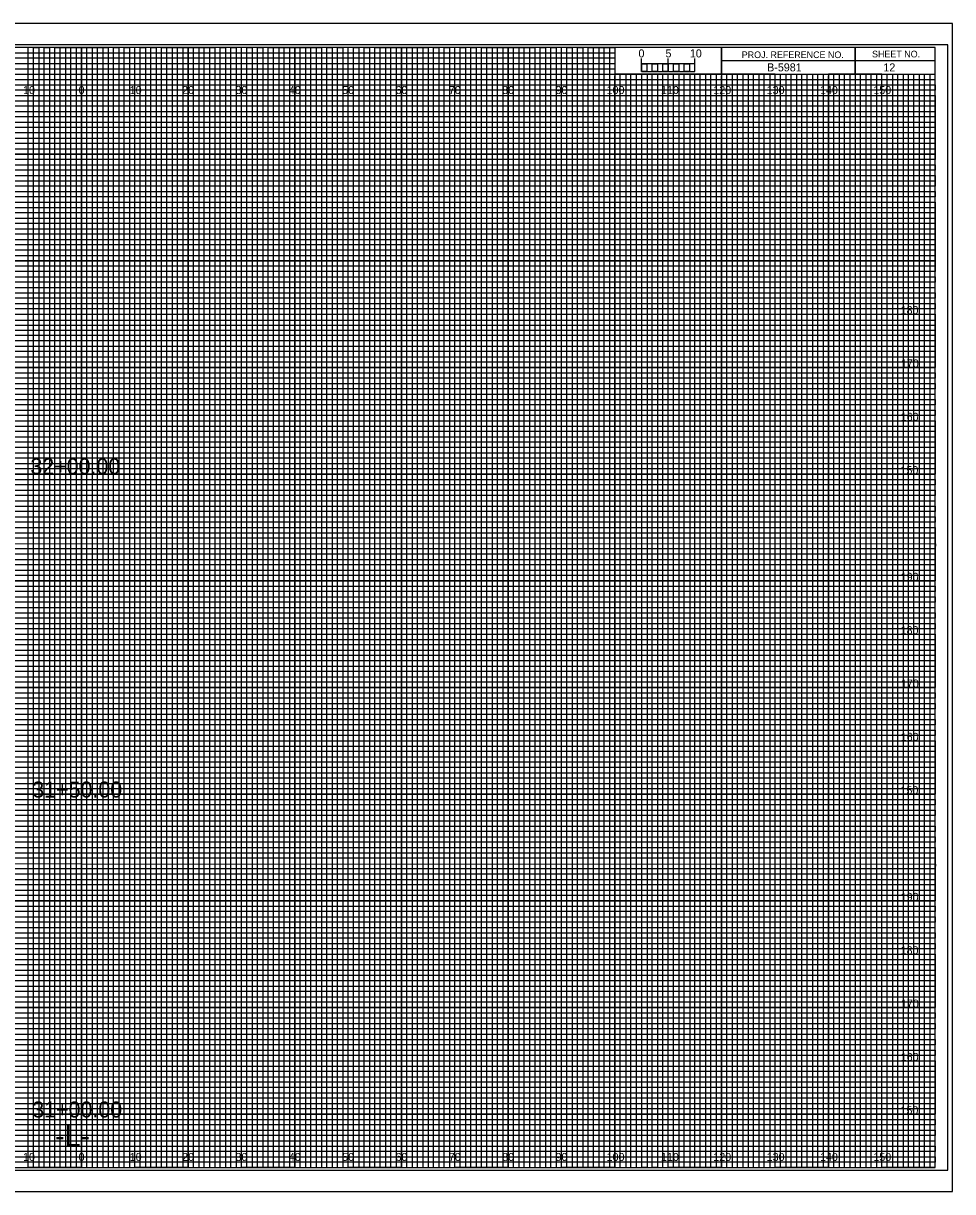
# Model space of a CAD drawing. Extents: x -13 to 323, y -5 to 434.
# Drawn here: x 149.1 to 323.3, y -4.5 to 214.5 of the extents above; entities that cross this region are included whole.
import ezdxf

# ---------------------------------------------------------------- set-up
doc = ezdxf.new("R2010")
doc.units = 0
for name, color, linetype in [('Exist Cross Section Cell', 7, 'Continuous'), ('Exist XS Center Line Elevation Label', 7, 'Continuous'), ('Exist XS Ground Line', 7, 'Continuous'), ('Prop CMT Concrete Structures', 7, 'Continuous'), ('Prop CMT Guardrail Graphics', 7, 'Continuous'), ('Prop CMT Pvmt Course 1', 7, 'Continuous'), ('Prop CMT Pvmt Course 2', 7, 'Continuous'), ('Prop CMT Pvmt Course 3', 7, 'Continuous'), ('Prop CMT Pvmt Surface', 7, 'Continuous'), ('Prop CMT Shld Paved Course 1', 7, 'Continuous'), ('Prop CMT Shld Paved Course 2', 7, 'Continuous'), ('Prop CMT Shld Paved Course 3', 7, 'Continuous'), ('Prop CMT Subgrade Earthwork', 7, 'Continuous'), ('Prop XS Ditch Standard Text', 7, 'Continuous'), ('Prop XS SE Text', 7, 'Continuous'), ('Prop XS Side Slope Text', 7, 'Continuous'), ('Scratch_Level_0', 7, 'Continuous')]:
    doc.layers.add(name, color=color, linetype=linetype)

msp = doc.modelspace()

# ---------------------------------------------------------------- linework, layer by layer
at = {"layer": 'Exist XS Center Line Elevation Label'}
for points in [[(145, 0), (155, 0), (155, 210), (165, 210), (165, 0), (175, 0), (175, 210), (185, 210), (185, 0), (195, 0), (195, 210), (205, 210), (205, 0), (215, 0), (215, 210), (225, 210), (225, 0), (235, 0), (235, 210), (245, 210), (245, 0), (255, 0), (255, 210), (259.93, 210), (260, 210), (260, 205), (264.99, 205), (264.99, 0), (275, 0), (275, 205), (285, 205), (285, 0), (295, 0), (295, 205), (305, 205), (305, 0), (315, 0), (315, 205)], [(0, 205), (275, 205)], [(0, 185), (320, 185), (320, 195), (0, 195)], [(0, 165), (320, 165), (320, 175), (0, 175)], [(0, 145), (320, 145), (320, 155), (0, 155)], [(0, 125), (320, 125), (320, 135), (0, 135)], [(0, 105), (320, 105), (320, 115), (0, 115)], [(0, 85), (320, 85), (320, 95), (0, 95)], [(0, 65), (320, 65), (320, 75), (0, 75)], [(0, 45), (320, 45), (320, 55), (0, 55)], [(0, 25), (320, 25), (320, 35), (0, 35)], [(0, 5), (320, 5), (320, 15), (0, 15)]]:
    msp.add_lwpolyline(points, dxfattribs=at)
at = {"layer": 'Exist XS Ground Line'}
for p, q in [((150, 210), (140, 210)), ((150, 0), (150, 210)), ((170, 210), (160, 210)), ((160, 210), (160, 0)), ((170, 0), (170, 210)), ((190, 210), (180, 210)), ((180, 210), (180, 0)), ((190, 0), (190, 210)), ((210, 210), (200, 210)), ((200, 210), (200, 0)), ((210, 0), (210, 210)), ((230, 210), (220, 210)), ((220, 210), (220, 0)), ((230, 0), (230, 210)), ((250, 210), (240, 210)), ((240, 210), (240, 0)), ((250, 0), (250, 210)), ((260, 210), (260, 0)), ((270, 0), (270, 205)), ((290, 205), (280, 205)), ((280, 205), (280, 0)), ((290, 0), (290, 205)), ((310, 205), (300, 205)), ((300, 205), (300, 0)), ((310, 0), (310, 205)), ((160, 0), (150, 0)), ((180, 0), (170, 0)), ((200, 0), (190, 0)), ((220, 0), (210, 0)), ((240, 0), (230, 0)), ((260, 0), (250, 0)), ((280, 0), (270, 0)), ((300, 0), (290, 0)), ((320, 0), (310, 0)), ((320, 0), (320, 0))]:
    msp.add_line(p, q, dxfattribs=at)
for points in [[(0, 200), (320, 200), (320, 190), (0, 190)], [(0, 180), (320, 180), (320, 170), (0, 170)], [(0, 160), (320, 160), (320, 150), (0, 150)], [(0, 140), (320, 140), (320, 130), (0, 130)], [(0, 120), (320, 120), (320, 110), (0, 110)], [(0, 100), (320, 100), (320, 90), (0, 90)], [(0, 80), (320, 80), (320, 70), (0, 70)], [(0, 60), (320, 60), (320, 50), (0, 50)], [(0, 40), (320, 40), (320, 30), (0, 30)], [(0, 20), (320, 20), (320, 10), (0, 10)]]:
    msp.add_lwpolyline(points, dxfattribs=at)
at = {"layer": 'Prop CMT Pvmt Course 1'}
for p, q in [((323.3, 214.5), (-13.4, 214.5)), ((-13.4, -4.5), (323.3, -4.5))]:
    msp.add_line(p, q, dxfattribs=at)
at = {"layer": 'Prop CMT Pvmt Course 2'}
msp.add_lwpolyline([(-13.4, -4.5), (323.3, -4.5), (323.3, 214.5), (-13.4, 214.5)], close=True, dxfattribs=at)
at = {"layer": 'Prop CMT Pvmt Course 3'}
msp.add_lwpolyline([(-10.8, -0.5), (322.4, -0.5), (322.4, 210.5), (-10.8, 210.5)], close=True, dxfattribs=at)
at = {"layer": 'Prop CMT Shld Paved Course 1'}
for p, q in [((305, 210), (305, 205)), ((305, 205), (305, 210)), ((280, 207.5), (280, 205)), ((320, 207.49), (280, 207.49)), ((280, 205), (320, 205))]:
    msp.add_line(p, q, dxfattribs=at)
for points in [[(320, 210), (0, 210), (0, 0), (320, 0)], [(280, 210), (260, 210), (260, 205.03), (280, 205.03)], [(320, 210), (280, 210), (280, 205), (320, 205)]]:
    msp.add_lwpolyline(points, close=True, dxfattribs=at)
at = {"layer": 'Prop CMT Shld Paved Course 2'}
for p, q in [((267, 205), (266.01, 205)), ((266.01, 205), (266.01, 0)), ((267, 0), (267, 205)), ((269, 205), (268, 205)), ((268, 205), (268, 0)), ((269, 0), (269, 205)), ((266.01, 0), (265, 0)), ((268, 0), (267, 0))]:
    msp.add_line(p, q, dxfattribs=at)
for points in [[(150, 0), (151, 0), (151, 210), (152, 210), (152, 0)], [(152, 0), (153, 0), (153, 210), (154, 210), (154, 0)], [(155, 0), (156, 0), (156, 210), (157, 210), (157, 0)], [(157, 0), (158, 0), (158, 210), (159, 210), (159, 0)], [(160, 0), (161, 0), (161, 210), (162, 210), (162, 0)], [(162, 0), (163, 0), (163, 210), (164, 210), (164, 0)], [(165, 0), (166, 0), (166, 210), (167, 210), (167, 0)], [(167, 0), (168, 0), (168, 210), (169, 210), (169, 0)], [(170, 0), (171, 0), (171, 210), (172, 210), (172, 0)], [(172, 0), (173, 0), (173, 210), (174, 210), (174, 0)], [(175, 0), (176, 0), (176, 210), (177, 210), (177, 0)], [(177, 0), (178, 0), (178, 210), (179, 210), (179, 0)], [(180, 0), (181, 0), (181, 210), (182, 210), (182, 0)], [(182, 0), (183, 0), (183, 210), (184, 210), (184, 0)], [(185, 0), (186, 0), (186, 210), (187, 210), (187, 0)], [(187, 0), (188, 0), (188, 210), (189, 210), (189, 0)], [(190, 0), (191, 0), (191, 210), (192, 210), (192, 0)], [(192, 0), (193, 0), (193, 210), (194, 210), (194, 0)], [(195, 0), (196, 0), (196, 210), (197, 210), (197, 0)], [(197, 0), (198, 0), (198, 210), (199, 210), (199, 0)], [(200, 0), (201, 0), (201, 210), (202, 210), (202, 0)], [(202, 0), (203, 0), (203, 210), (204, 210), (204, 0)], [(205, 0), (206, 0), (206, 210), (207, 210), (207, 0)], [(207, 0), (208, 0), (208, 210), (209, 210), (209, 0)], [(210, 0), (211, 0), (211, 210), (212, 210), (212, 0)], [(212, 0), (213, 0), (213, 210), (214, 210), (214, 0)], [(215, 0), (216, 0), (216, 210), (217, 210), (217, 0)], [(217, 0), (218, 0), (218, 210), (219, 210), (219, 0)], [(220, 0), (221, 0), (221, 210), (222, 210), (222, 0)], [(222, 0), (223, 0), (223, 210), (224, 210), (224, 0)], [(225, 0), (226, 0), (226, 210), (227, 210), (227, 0)], [(227, 0), (228, 0), (228, 210), (229, 210), (229, 0)], [(230, 0), (231, 0), (231, 210), (232, 210), (232, 0)], [(232, 0), (233, 0), (233, 210), (234, 210), (234, 0)], [(235, 0), (236, 0), (236, 210), (237, 210), (237, 0)], [(237, 0), (238, 0), (238, 210), (239, 210), (239, 0)], [(240, 0), (241, 0), (241, 210), (242, 210), (242, 0)], [(242, 0), (243, 0), (243, 210), (244, 210), (244, 0)], [(245, 0), (246, 0), (246, 210), (247, 210), (247, 0)], [(247, 0), (248, 0), (248, 210), (249, 210), (249, 0)], [(250, 0), (251, 0), (251, 210), (252, 210), (252, 0)], [(252, 0), (253, 0), (253, 210), (254, 210), (254, 0)], [(255, 0), (256, 0), (256, 210), (257, 210), (257, 0)], [(257, 0), (258, 0), (258, 210), (259, 210), (259, 0)], [(260, 0), (261, 0), (261, 205), (262.02, 205), (262.02, 0)], [(262, 0), (263, 0), (263, 205), (263.99, 205), (263.99, 0)], [(270, 0), (270.98, 0), (270.98, 205), (272, 205), (272, 0)], [(272, 0), (273, 0), (273, 205), (274.05, 205), (274.05, 0)], [(275, 0), (276, 0), (276, 205), (277, 205), (277, 0)], [(277, 0), (278, 0), (278, 205), (279, 205), (279, 0)], [(280, 0), (281, 0), (281, 205), (282, 205), (282, 0)], [(282, 0), (283, 0), (283, 205), (284, 205), (284, 0)], [(285, 0), (286, 0), (286, 205), (287, 205), (287, 0)], [(287, 0), (288, 0), (288, 205), (289, 205), (289, 0)], [(290, 0), (291, 0), (291, 205), (292, 205), (292, 0)], [(292, 0), (293, 0), (293, 205), (294, 205), (294, 0)], [(295, 0), (296, 0), (296, 205), (297, 205), (297, 0)], [(297, 0), (298, 0), (298, 205), (299, 205), (299, 0)], [(300, 0), (301, 0), (301, 205), (302, 205), (302, 0)], [(302, 0), (303, 0), (303, 205), (304, 205), (304, 0)], [(305, 0), (306, 0), (306, 205), (307, 205), (307, 0)], [(307, 0), (308, 0), (308, 205), (309, 205), (309, 0)], [(310, 0), (311, 0), (311, 205), (312, 205), (312, 0)], [(312, 0), (313, 0), (313, 205), (314, 205), (314, 0)], [(315, 0), (316, 0), (316, 205), (317, 205), (317, 0)], [(317, 0), (318, 0), (318, 205), (319, 205), (319, 0)]]:
    msp.add_lwpolyline(points, dxfattribs=at)
at = {"layer": 'Prop CMT Shld Paved Course 3'}
for p, q in [((265, 205.49), (265, 207.9)), ((265, 206.9), (265, 207.9)), ((270, 205.49), (270, 207.9)), ((275, 205.49), (275, 207.9)), ((275, 206.9), (275, 207.9))]:
    msp.add_line(p, q, dxfattribs=at)
for points in [[(275, 206.9), (265, 206.9), (265, 205.49), (275, 205.49)], [(265, 206.9), (266, 206.9), (266, 205.49), (265, 205.49)], [(267, 206.9), (268, 206.9), (268, 205.49), (267, 205.49)], [(269, 206.9), (270, 206.9), (270, 205.49), (269, 205.49)], [(271, 206.9), (272, 206.9), (272, 205.49), (271, 205.49)], [(273, 206.9), (274, 206.9), (274, 205.49), (273, 205.49)]]:
    msp.add_lwpolyline(points, close=True, dxfattribs=at)
at = {"layer": 'Prop CMT Subgrade Earthwork'}
for p, q in [((150, 0), (150, 210)), ((160, 0), (160, 210)), ((170, 0), (170, 210)), ((180, 0), (180, 210)), ((190, 0), (190, 210)), ((200, 0), (200, 210)), ((210, 0), (210, 210)), ((220, 0), (220, 210)), ((230, 0), (230, 210)), ((240, 0), (240, 210)), ((250, 0), (250, 210)), ((260, 0), (260, 204.69)), ((270, 0), (270, 204.69)), ((280, 0), (280, 204.69)), ((290, 0), (290, 204.69)), ((300, 0), (300, 204.69)), ((310, 0), (310, 204.69)), ((0, 200), (320, 200)), ((0, 190), (320, 190)), ((0, 180), (320, 180)), ((0, 170), (320, 170)), ((0, 160), (320, 160)), ((0, 150), (320, 150)), ((0, 140), (320, 140)), ((0, 130), (320, 130)), ((0, 120), (320, 120)), ((0, 110), (320, 110)), ((0, 100), (320, 100)), ((0, 90), (320, 90)), ((0, 80), (320, 80)), ((0, 70), (320, 70)), ((0, 60), (320, 60)), ((0, 50), (320, 50)), ((0, 40), (320, 40)), ((0, 30), (320, 30)), ((0, 20), (320, 20)), ((0, 10), (320, 10))]:
    msp.add_line(p, q, dxfattribs=at)
at = {"layer": 'Scratch_Level_0'}
for p, q in [((0, 209), (260, 209)), ((260, 209), (260, 207.98)), ((260, 207.98), (0, 207.98)), ((0, 207), (260, 207)), ((260, 205.89), (0, 205.89)), ((260, 207), (260, 205.89)), ((0, 204), (320, 204))]:
    msp.add_line(p, q, dxfattribs=at)
for points in [[(0, 203), (270, 203), (320, 203), (320, 202), (0, 202)], [(0, 201), (320, 201), (320, 199), (0, 199)], [(0, 198), (320, 198), (320, 197), (0, 196.98)], [(0, 196), (320, 196), (320, 194), (0, 194)], [(0, 193), (320, 193), (320, 192), (0, 192)], [(0, 191), (320, 191), (320, 189), (0, 189)], [(0, 188), (320, 188), (320, 187), (0, 187)], [(0, 186), (320, 186), (320, 184), (0, 184)], [(0, 183), (320, 183), (320, 182), (0, 182)], [(0, 181), (320, 181), (320, 179), (0, 179)], [(0, 178), (320, 178), (320, 177), (0, 177)], [(0, 176), (320, 176), (320, 173.95), (320, 173), (320, 172), (0, 172)], [(0, 174), (320, 174), (320, 173), (0, 173)], [(0, 171), (320, 171), (320, 169), (0, 169.03)], [(0, 169.03), (320, 169), (320, 168), (0, 168)], [(0, 167), (320, 167), (320, 166), (0, 166)], [(0, 164), (320, 164), (320, 163), (0, 163)], [(0, 162), (320, 162), (320, 161), (0, 161)], [(-0.07, 158.89), (320, 158.89), (320, 157.88), (-0.07, 157.88)], [(0, 157), (320, 157), (320, 156), (0, 156)], [(0, 154), (320, 154), (320, 153), (0, 153)], [(0, 152), (320, 152), (320, 151), (0, 151)], [(0, 149), (320, 149), (320, 148), (0, 148)], [(0, 147), (320, 147), (320, 146), (0, 146)], [(0, 144), (320, 144), (320, 143), (0, 143)], [(0, 142), (320, 142), (320, 141), (0, 141)], [(0, 139), (320, 139), (319.99, 137.98), (0, 138)], [(0, 137), (320, 137), (320, 136), (0, 136)], [(0, 134), (320, 134), (320, 133), (0, 133)], [(0, 132), (320, 132), (320, 131), (0, 131)], [(0, 129), (320, 129), (320, 128), (0, 128)], [(0, 127), (320, 127), (320, 126), (0, 126)], [(0, 124), (320, 124), (320, 123), (0, 123)], [(0, 122), (320, 122), (320, 121), (0, 121)], [(0, 119), (320, 119), (320, 118), (0, 118)], [(0, 116.99), (320.07, 116.91), (320, 116), (0, 116)], [(0, 114), (320, 114), (320, 113), (0, 113)], [(0, 112), (320, 112), (320, 111), (0, 111)], [(0, 109), (320, 109), (320, 108), (0, 108)], [(0, 107), (320, 107), (320, 106), (0, 106)], [(0, 104), (320, 104), (320, 103), (0, 103)], [(0, 102), (320, 102), (320, 101), (0, 101)], [(0, 99), (320, 99), (320, 98), (0, 98)], [(0, 97), (320, 97), (320, 96), (0, 96)], [(0, 94), (320, 94), (320, 93), (0, 93)], [(0, 92), (320, 92), (320, 91), (0, 91)], [(0, 89), (320, 89), (320, 88), (0, 88)], [(0, 87), (320, 87), (320, 86), (0, 86)], [(0, 84), (320, 84), (320, 83), (0, 83)], [(0, 82), (320, 82), (320, 81), (0, 81)], [(0, 79), (320, 79), (319.99, 77.98), (0, 78)], [(0, 77), (320, 77), (320, 76), (0, 76)], [(0, 74), (320, 74), (320, 73), (0, 73)], [(0, 72), (320, 72), (320, 71), (0, 71)], [(0, 69), (320, 69), (320, 68), (0, 68)], [(0, 67), (320, 67), (320, 66), (0, 66)], [(0, 64), (320, 64), (320, 63), (0, 63)], [(0, 62), (320, 62), (320, 61), (0, 61)], [(0, 59), (320, 59), (320, 58), (0, 58)], [(0, 56.99), (320.07, 56.91), (320, 56), (0, 56)], [(0, 54), (320, 54), (320, 53), (0, 53)], [(0, 52), (320, 52), (320, 51), (0, 51)], [(0, 49), (320, 49), (320, 48), (0, 48)], [(0, 47), (320, 47), (320, 46), (0, 46)], [(0, 44), (320, 44), (320, 43), (0, 43)], [(0, 42), (320, 42), (320, 41), (0, 41)], [(0, 39), (320, 39), (320, 38), (0, 38)], [(0, 37), (320, 37), (320, 36), (0, 36)], [(0, 34), (320, 34), (320, 33), (0, 33)], [(0, 32), (320, 32), (320, 31), (0, 31)], [(0, 29), (320, 29), (320, 28), (0, 28)], [(0, 27), (320, 27), (320, 26), (0, 26)], [(0, 24), (320, 24), (320, 23), (0, 23)], [(0, 22), (320, 22), (320, 21), (0, 21)], [(0, 19), (320, 19), (320, 18), (0, 18)], [(0, 17), (320, 17), (320, 16), (0, 16)], [(0, 14), (320, 14), (320, 13), (0, 13)], [(0, 12), (320, 12), (320, 11), (0, 11)], [(0, 9), (320, 9), (320, 8), (0, 8)], [(0, 7), (320, 7), (320, 6), (0, 6)], [(0, 4), (320, 4), (320, 3), (0, 3)], [(0, 2), (320, 2), (320, 1), (0, 1)]]:
    msp.add_lwpolyline(points, dxfattribs=at)

# ---------------------------------------------------------------- texts
at = {"layer": 'Exist Cross Section Cell'}
for s, p in [('180', (313.55, 160)), ('170', (313.61, 150)), ('160', (313.57, 140)), ('150', (313.52, 130)), ('190', (313.57, 110)), ('180', (313.55, 100)), ('170', (313.61, 90)), ('160', (313.57, 80)), ('150', (313.52, 70)), ('190', (313.57, 50)), ('180', (313.55, 40)), ('170', (313.61, 30)), ('160', (313.57, 20)), ('150', (313.52, 10))]:
    msp.add_text(s, height=1.5, dxfattribs=at).set_placement(p)
at = {"layer": 'Prop CMT Concrete Structures'}
msp.add_text('12', height=1.5, dxfattribs=at).set_placement((310.32, 205.5))
at = {"layer": 'Prop CMT Guardrail Graphics'}
for s, p in [('5', (269.47, 208.12)), ('10', (274.04, 208.12))]:
    msp.add_text(s, height=1.5, dxfattribs=at).set_placement(p)
at = {"layer": 'Prop CMT Pvmt Surface'}
for s, p in [('32+00.00', (150.41, 129.97)), ('31+50.00', (150.77, 69.38)), ('31+00.00', (150.77, 9.4))]:
    msp.add_text(s, height=3, dxfattribs=at).set_placement(p)
at = {"layer": 'Prop CMT Shld Paved Course 1'}
for s, p in [('PROJ. REFERENCE NO.', (283.77, 207.99)), ('SHEET NO.', (308.19, 208.12))]:
    msp.add_text(s, height=1.25, dxfattribs=at).set_placement(p)
at = {"layer": 'Prop CMT Shld Paved Course 3'}
msp.add_text('0', height=1.5, dxfattribs=at).set_placement((264.41, 208.12))
at = {"layer": 'Prop XS Ditch Standard Text'}
for s, p in [('10', (149.04, 201.25)), ('0', (159.45, 201.25)), ('0', (159.45, 201.25)), ('10', (169.04, 201.25)), ('20', (178.86, 201.25)), ('30', (188.86, 201.25)), ('40', (198.86, 201.25)), ('50', (208.86, 201.25)), ('60', (218.86, 201.25)), ('70', (228.86, 201.25)), ('80', (238.86, 201.25)), ('90', (248.86, 201.25)), ('100', (258.44, 201.25)), ('110', (268.62, 201.25)), ('120', (278.44, 201.25)), ('130', (288.44, 201.25)), ('140', (298.44, 201.25)), ('150', (308.44, 201.25)), ('10', (149.04, 1.25)), ('0', (159.45, 1.25)), ('0', (159.45, 1.25)), ('10', (169.04, 1.25)), ('20', (178.86, 1.25)), ('30', (188.86, 1.25)), ('40', (198.86, 1.25)), ('50', (208.86, 1.25)), ('60', (218.86, 1.25)), ('70', (228.86, 1.25)), ('80', (238.86, 1.25)), ('90', (248.86, 1.25)), ('100', (258.44, 1.25)), ('110', (268.62, 1.25)), ('120', (278.44, 1.25)), ('130', (288.44, 1.25)), ('140', (298.44, 1.25)), ('150', (308.44, 1.25))]:
    msp.add_text(s, height=1.5, dxfattribs=at).set_placement(p)
at = {"layer": 'Prop XS SE Text'}
msp.add_text('-L-', height=4, dxfattribs=at).set_placement((155.06, 4))
at = {"layer": 'Prop XS Side Slope Text'}
msp.add_text('B-5981', height=1.5, dxfattribs=at).set_placement((288.53, 205.5))

doc.saveas('drawing.dxf')
